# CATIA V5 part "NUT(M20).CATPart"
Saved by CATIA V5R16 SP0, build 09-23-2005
Part number: NUT(M20)
Source: bought
Bounding box of the stored display mesh (mm): x -17.321 to 17.321, y -15 to 15, z -3 to 8
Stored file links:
  C:\V5_education\CATIA Data\ASD\Power Transmission Gear Assembly\Assembly Data\NUT(M20).CATPart
  C:\usr\gt1\projet\valve\doc\doc_2005\comp\M4.CATPart
  C:\usr\gt1\projet\valve\doc\doc_2005\cylinder1\hexagon.CATPart
  C:\Work\Workbench\KWA\CATPart\Gear\pump_kimm_2\pump_kimm_2\limiter\max_flow_block.CATProduct
  C:\Work\Workbench\KWA\CATPart\Gear\pump_kimm_2\pump_kimm_2\limiter\flow_nut.CATPart
  C:\V5_education\Assemble Design\CATProduct\Power Transmission Gear\Axis.CATPart
  C:\V5_education\CATIA Data\ASD\Power Transmission Gear Assembly\Assembly Data\Power Transmission Gear Assembly.CATProduct
  C:\V5_education\CATIA Data\ASD\Power Transmission Gear Assembly\Assembly Data\Power Transmission Gear.CATPart
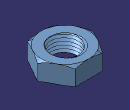
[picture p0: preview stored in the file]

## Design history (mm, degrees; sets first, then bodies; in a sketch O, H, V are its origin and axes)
External parameters (linked from other documents)
  External.M = 20 mm
  External.H = 30 mm
Set1
  DatumSurface1: linked copy from another document
Set2 "M24 Helix Body"
  Point1: (0, -10.4, -13), relative to Point2
  Line1: type PtDir, RefPoint Point2, Direction xy-plane, Start -20, End 25
  Helix1: Direction Line1, RefPoint Point1, Pitch 2, Height 25, TaperAngle 0
  Sweep1: type Segment, GuideCrv Helix1, Length1 2, Length2 0, Angle 60, DraftDirection xy-plane
  Sweep2: type Segment, GuideCrv Helix1, Length1 2, Length2 0, Angle 60, DraftDirection xy-plane
  Trim1: Trimmed (Sweep1; Sweep2)
Set3 "Reference Data"
  Point2 "Center Point": (0, 0, 0)
  Plane1: type Offset, RefPlane xy-plane, Offset -3
Body1 (main body)
  Sketch1 on xy-plane, origin (0, 0, 0), H (0, 1, 0), V (-1, 0, 0)
    point P1 (0, 0)
    point P2 (15, -8.6603)
    point P3 (15, 8.6603)
    point P4 (0, 17.3205)
    point P5 (-15, 8.6603)
    point P6 (-15, -8.6603)
    point P7 (0, -17.3205)
    point P8 (15, 0)
    line L1 (15, -8.6603) -> (15, 8.6603)
    line L2 (15, 8.6603) -> (0, 17.3205)
    line L3 (0, 17.3205) -> (-15, 8.6603)
    line L4 (-15, 8.6603) -> (-15, -8.6603)
    line L5 (-15, -8.6603) -> (0, -17.3205)
    line L6 (0, -17.3205) -> (15, -8.6603)
    construction line L7 (0, 0) -> (15, 0)
    construction arc A1 centre (0, 0) radius 17.3205 from (15, -8.6603) to (0, -17.3205) ccw
    construction arc A2 centre (-15, -8.6603) radius 17.3205 from (-15, 8.6603) to (0, -17.3205) cw
    construction arc A3 centre (15, 8.6603) radius 17.3205 from (0, 17.3205) to (15, -8.6603) ccw
    point P9 (-15, -8.6603)
    point P10 (15, 8.6603)
    distance L1 L4 = 30 {= External.H}
    coincidence: P1 O, A1 P2, A1 P3, A1 P4, A1 P5, A1 P6, A1 P7, A2 P5, A2 P7, A2 P1, P9 P6, A3 P4, A3 P2, A3 P1, P10 P3
    horizontal: L7 H
    midpoint: P8 L1
  Sketch2 on yz-plane, origin (0, 0, 0), H (0, 1, 0), V (0, 0, 1)
    line L1 (-17.3205, 6.6603) -> (-15, 8)
    point P2 (-15, 8)
    line L2 (-15, 8) -> (-9.3135, 8)
    line L3 (-17.3205, -8) -> (-9.3135, -8)
    line L4 (-8.6469, 7.3333) -> (-8.6469, -7.3333)
    line L5 (-17.3205, 6.6603) -> (-17.3205, -8)
    line L6 (-9.3135, 8) -> (-8.6469, 7.3333)
    point P3 (-9.3135, 8)
    point P4 (-8.6469, 7.3333)
    line L7 (-9.3135, -8) -> (-8.6469, -7.3333)
    point P5 (-9.3135, -8)
    point P6 (-8.6469, -7.3333)
    angle L1 L2 = 30
    distance P2 V = 15 {= External.H/2}
    distance L4 V = 8.6469
    distance L2 L3 = 16 {= External.M * 4 / 5}
    distance L5 V = 17.3205 {= External.H / sqrt( 3 )}
    angle L2 L6 = 45
    length L6 H = 0.6667 {= External.M/30}
    horizontal: L2 H, L3 H
    vertical: L4 V, L5 V
    symmetry: P3 P5 H, P4 P6 H
  Shaft1: profile Sketch2, axis Sketch2.V, angle 360
  Pocket1: profile Sketch1, direction (0, 0, -1), through (limit type 6), opposite side through (limit type 6), outer side
  AssyPrtSPLIT1: _MechModInactiveResultOUT result of AssyPrtSPLIT1, deactivated
  Split1: SplitPlane Trim1
  Split2: SplitPlane Plane1
  AssyPrtSPLIT2: SplitPlane DatumSurface1, _MechModInactiveResultOUT result of AssyPrtSPLIT2, deactivated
